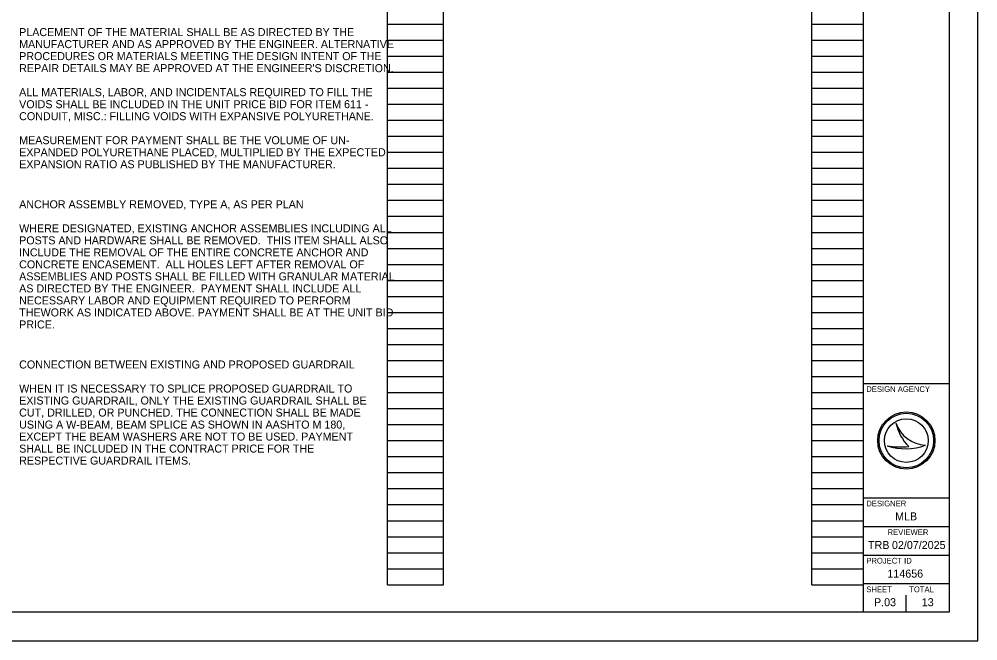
# Model space of a CAD drawing. Extents: x 0 to 34, y 0 to 22.
# Drawn here: x 17.24 to 34, y 0 to 10.87 of the extents above; entities that cross this region are included whole.
import ezdxf

# ---------------------------------------------------------------- set-up
doc = ezdxf.new("R2010")
doc.units = 0
for name, color, linetype in [('SH_Border', 7, 'Continuous'), ('SH_Cut_Line', 7, 'Continuous'), ('SH_Data', 7, 'Continuous'), ('SH_Text', 7, 'Continuous')]:
    doc.layers.add(name, color=color, linetype=linetype)

msp = doc.modelspace()

# ---------------------------------------------------------------- linework, layer by layer
at = {"layer": 'SH_Border'}
for p, q in [((32, 0.5), (32, 21.5)), ((32, 4.5), (33.5, 4.5)), ((32, 2.5), (33.5, 2.5)), ((32, 2), (33.5, 2)), ((32, 1.5), (33.5, 1.5)), ((32, 1), (33.5, 1))]:
    msp.add_line(p, q, dxfattribs=at)
msp.add_lwpolyline([(1.5, 21.5), (33.5, 21.5), (33.5, 0.5), (1.5, 0.5)], close=True, dxfattribs=at)
at = {"layer": 'SH_Cut_Line'}
msp.add_lwpolyline([(0, 0), (34, 0), (34, 22), (0, 22)], close=True, dxfattribs=at)
at = {"layer": 'SH_Data'}
for p, q in [((23.68, 0.98), (23.68, 21.14)), ((24.66, 0.98), (24.66, 21.14)), ((31.1, 0.98), (31.1, 21.14)), ((32, 0.98), (32, 21.14)), ((23.68, 10.78), (24.66, 10.78)), ((31.1, 10.78), (32, 10.78)), ((23.68, 10.5), (24.66, 10.5)), ((31.1, 10.5), (32, 10.5)), ((23.68, 10.22), (24.66, 10.22)), ((31.1, 10.22), (32, 10.22)), ((23.68, 9.94), (24.66, 9.94)), ((31.1, 9.94), (32, 9.94)), ((23.68, 9.66), (24.66, 9.66)), ((31.1, 9.66), (32, 9.66)), ((23.68, 9.38), (24.66, 9.38)), ((31.1, 9.38), (32, 9.38)), ((23.68, 9.1), (24.66, 9.1)), ((31.1, 9.1), (32, 9.1)), ((23.68, 8.82), (24.66, 8.82)), ((31.1, 8.82), (32, 8.82)), ((23.68, 8.54), (24.66, 8.54)), ((31.1, 8.54), (32, 8.54)), ((23.68, 8.26), (24.66, 8.26)), ((31.1, 8.26), (32, 8.26)), ((23.68, 7.98), (24.66, 7.98)), ((31.1, 7.98), (32, 7.98)), ((23.68, 7.7), (24.66, 7.7)), ((31.1, 7.7), (32, 7.7)), ((23.68, 7.42), (24.66, 7.42)), ((31.1, 7.42), (32, 7.42)), ((23.68, 7.14), (24.66, 7.14)), ((31.1, 7.14), (32, 7.14)), ((23.68, 6.86), (24.66, 6.86)), ((31.1, 6.86), (32, 6.86)), ((23.68, 6.58), (24.66, 6.58)), ((31.1, 6.58), (32, 6.58)), ((23.68, 6.3), (24.66, 6.3)), ((31.1, 6.3), (32, 6.3)), ((23.68, 6.02), (24.66, 6.02)), ((31.1, 6.02), (32, 6.02)), ((23.68, 5.74), (24.66, 5.74)), ((31.1, 5.74), (32, 5.74)), ((23.68, 5.46), (24.66, 5.46)), ((31.1, 5.46), (32, 5.46)), ((23.68, 5.18), (24.66, 5.18)), ((31.1, 5.18), (32, 5.18)), ((23.68, 4.9), (24.66, 4.9)), ((31.1, 4.9), (32, 4.9)), ((23.68, 4.62), (24.66, 4.62)), ((31.1, 4.62), (32, 4.62)), ((23.68, 4.34), (24.66, 4.34)), ((31.1, 4.34), (32, 4.34)), ((23.68, 4.06), (24.66, 4.06)), ((31.1, 4.06), (32, 4.06)), ((23.68, 3.78), (24.66, 3.78)), ((31.1, 3.78), (32, 3.78)), ((32.567, 3.81), (32.567, 3.81)), ((23.68, 3.5), (24.66, 3.5)), ((31.1, 3.5), (32, 3.5)), ((32.417, 3.41), (32.417, 3.41)), ((32.75, 3.5), (32.75, 3.5)), ((33.087, 3.419), (33.087, 3.419)), ((23.68, 3.22), (24.66, 3.22)), ((31.1, 3.22), (32, 3.22)), ((23.68, 2.94), (24.66, 2.94)), ((31.1, 2.94), (32, 2.94)), ((23.68, 2.66), (24.66, 2.66)), ((31.1, 2.66), (32, 2.66)), ((23.68, 2.38), (24.66, 2.38)), ((31.1, 2.38), (32, 2.38)), ((23.68, 2.1), (24.66, 2.1)), ((31.1, 2.1), (32, 2.1)), ((23.68, 1.82), (24.66, 1.82)), ((31.1, 1.82), (32, 1.82)), ((23.68, 1.54), (24.66, 1.54)), ((31.1, 1.54), (32, 1.54)), ((23.68, 1.26), (24.66, 1.26)), ((31.1, 1.26), (32, 1.26)), ((23.68, 0.98), (24.66, 0.98)), ((31.1, 0.98), (32, 0.98)), ((32.375, 0.675), (32.375, 0.675)), ((32.75, 0.5), (32.75, 0.8))]:
    msp.add_line(p, q, dxfattribs=at)
for radius in [0.5, 0.477, 0.477, 0.382]:
    msp.add_circle((32.75, 3.5), radius, dxfattribs=at)
for centre, radius, start, end in [((33.116, 3.998), 0.58, 198.9257, 198.9319), ((33.347, 3.97), 0.796, 191.6379, 191.6421), ((33.116, 3.998), 0.58, 198.9319, 267.1657), ((33.347, 3.97), 0.796, 191.6421, 226.0947), ((32.739, 4.37), 1.013, 251.4576, 290.0832), ((32.648, 4.654), 1.266, 259.4964, 259.4995), ((32.739, 4.37), 1.013, 251.4527, 251.4576), ((32.648, 4.654), 1.266, 259.4995, 276.6672)]:
    msp.add_arc(centre, radius, start, end, dxfattribs=at)

# ---------------------------------------------------------------- texts
for s, height, p in [('DESIGN AGENCY', 0.1, (32.05, 4.35)), ('DESIGNER', 0.1, (32.05, 2.35)), ('MLB', 0.14, (32.554, 2.105)), ('REVIEWER', 0.1, (32.422, 1.85)), ('TRB', 0.14, (32.081, 1.605)), ('02/07/2025', 0.14, (32.499, 1.605)), ('PROJECT ID', 0.1, (32.05, 1.35)), ('114656', 0.14, (32.419, 1.105)), ('SHEET', 0.1, (32.05, 0.85)), ('TOTAL', 0.1, (32.8, 0.85)), ('P.03', 0.14, (32.185, 0.605)), ('13', 0.14, (33.02, 0.605))]:
    msp.add_text(s, height=height, dxfattribs=at).set_placement(p)
at = {"layer": 'SH_Text'}
for s, p in [('PLACEMENT OF THE MATERIAL SHALL BE AS DIRECTED BY THE ', (17.24, 10.57)), ('MANUFACTURER AND AS APPROVED BY THE ENGINEER. ALTERNATIVE ', (17.24, 10.36)), ('PROCEDURES OR MATERIALS MEETING THE DESIGN INTENT OF THE ', (17.24, 10.15)), ("REPAIR DETAILS MAY BE APPROVED AT THE ENGINEER'S DISCRETION.", (17.24, 9.94)), ('ALL MATERIALS, LABOR, AND INCIDENTALS REQUIRED TO FILL THE ', (17.24, 9.52)), ('VOIDS SHALL BE INCLUDED IN THE UNIT PRICE BID FOR ITEM 611 - ', (17.24, 9.31)), ('CONDUIT, MISC.: FILLING VOIDS WITH EXPANSIVE POLYURETHANE.', (17.24, 9.1)), ('MEASUREMENT FOR PAYMENT SHALL BE THE VOLUME OF UN-', (17.24, 8.68)), ('EXPANDED POLYURETHANE PLACED, MULTIPLIED BY THE EXPECTED ', (17.24, 8.47)), ('EXPANSION RATIO AS PUBLISHED BY THE MANUFACTURER.', (17.24, 8.26)), ('ANCHOR ASSEMBLY REMOVED, TYPE A, AS PER PLAN', (17.24, 7.56)), ('WHERE DESIGNATED, EXISTING ANCHOR ASSEMBLIES INCLUDING ALL ', (17.24, 7.14)), ('POSTS AND HARDWARE SHALL BE REMOVED.  THIS ITEM SHALL ALSO ', (17.24, 6.93)), ('INCLUDE THE REMOVAL OF THE ENTIRE CONCRETE ANCHOR AND ', (17.24, 6.72)), ('CONCRETE ENCASEMENT.  ALL HOLES LEFT AFTER REMOVAL OF ', (17.24, 6.51)), ('ASSEMBLIES AND POSTS SHALL BE FILLED WITH GRANULAR MATERIAL ', (17.24, 6.3)), ('AS DIRECTED BY THE ENGINEER.  PAYMENT SHALL INCLUDE ALL ', (17.24, 6.09)), ('NECESSARY LABOR AND EQUIPMENT REQUIRED TO PERFORM ', (17.24, 5.88)), ('THEWORK AS INDICATED ABOVE. PAYMENT SHALL BE AT THE UNIT BID ', (17.24, 5.67)), ('PRICE.', (17.24, 5.46)), ('CONNECTION BETWEEN EXISTING AND PROPOSED GUARDRAIL', (17.24, 4.76)), ('WHEN IT IS NECESSARY TO SPLICE PROPOSED GUARDRAIL TO ', (17.24, 4.34)), ('EXISTING GUARDRAIL, ONLY THE EXISTING GUARDRAIL SHALL BE ', (17.24, 4.13)), ('CUT, DRILLED, OR PUNCHED. THE CONNECTION SHALL BE MADE ', (17.24, 3.92)), ('USING A W-BEAM, BEAM SPLICE AS SHOWN IN AASHTO M 180, ', (17.24, 3.71)), ('EXCEPT THE BEAM WASHERS ARE NOT TO BE USED. PAYMENT ', (17.24, 3.5)), ('SHALL BE INCLUDED IN THE CONTRACT PRICE FOR THE ', (17.24, 3.29)), ('RESPECTIVE GUARDRAIL ITEMS.', (17.24, 3.08))]:
    msp.add_text(s, height=0.14, dxfattribs=at).set_placement(p)

doc.saveas('drawing.dxf')
